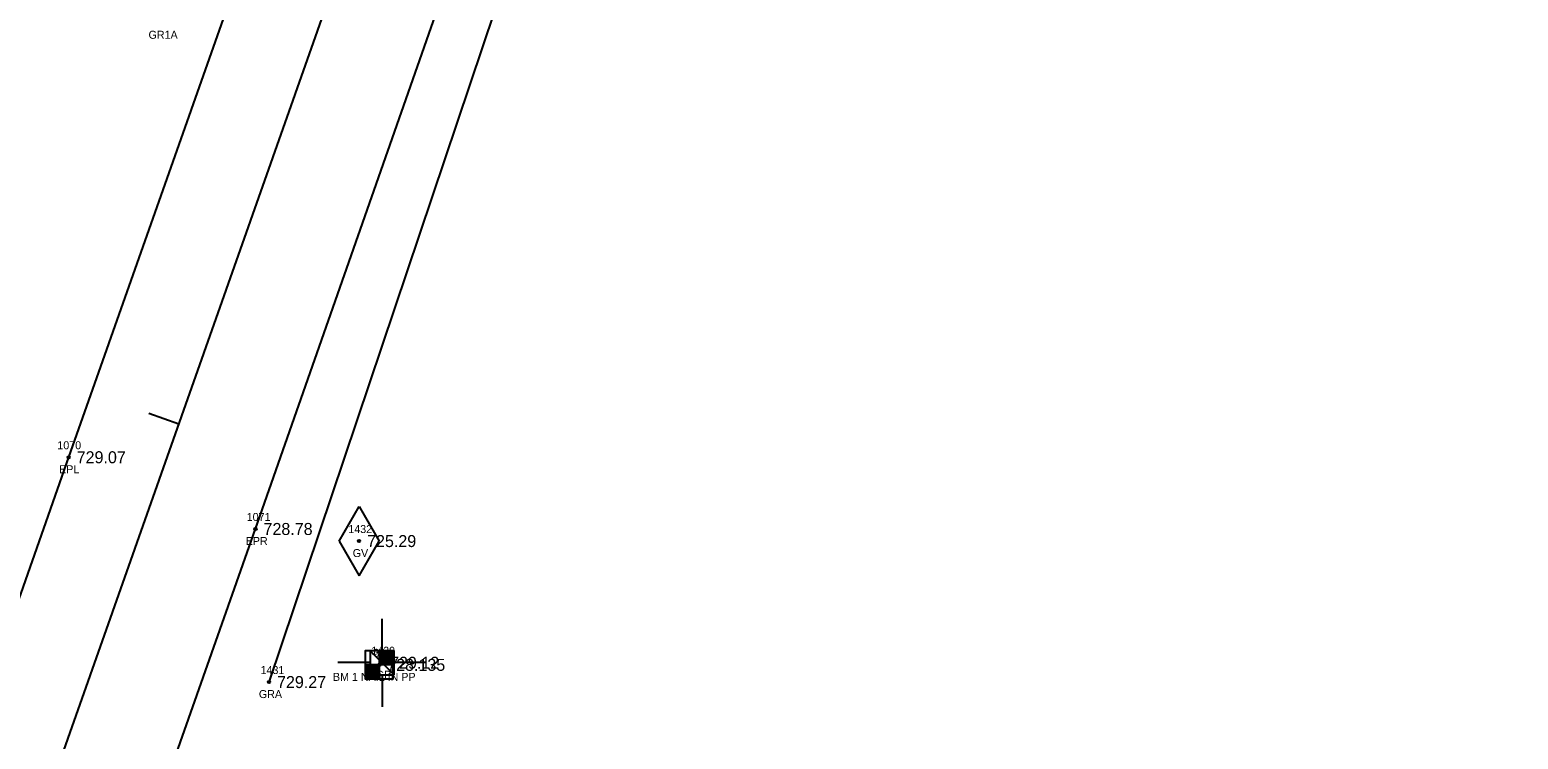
# Model space of a CAD drawing. Extents: x 1736563 to 1738032, y 1150548 to 1154248.
# Drawn here: x 1737322 to 1737508, y 1152422.1 to 1152510.8 of the extents above; entities that cross this region are included whole.
import ezdxf

# ---------------------------------------------------------------- set-up
doc = ezdxf.new("R2010")
doc.units = 0
for name, color, linetype in [('RD_EX_GuardRail', 7, 'Continuous'), ('RD_EX_GuardRail_txCode', 7, 'Continuous'), ('RD_EX_Road', 7, 'Continuous'), ('RD_EX_Road_txCode', 7, 'Continuous'), ('RD_EX_TX_GuardRail_ELEV', 7, 'Continuous'), ('RD_EX_TX_Road_ELEV', 7, 'Continuous'), ('RD_EX_TX_UT_ELEV', 7, 'Continuous'), ('RD_EX_UT', 7, 'Continuous'), ('RD_EX_UT_txCode', 7, 'Continuous'), ('RD_HC_Cl', 7, 'Continuous'), ('RD_HC_Data_Tic', 7, 'Continuous'), ('RD_HC_Survey', 7, 'Continuous'), ('RD_HC_Survey_ELEV', 7, 'Continuous'), ('RD_HC_Survey_txCode', 7, 'Continuous'), ('RD_SMD_Locator', 7, 'Continuous')]:
    doc.layers.add(name, color=color, linetype=linetype)

msp = doc.modelspace()

# ---------------------------------------------------------------- linework, layer by layer
at = {"layer": 'RD_EX_GuardRail'}
msp.add_lwpolyline([(1737351.87, 1152429.26), (1737391.13, 1152545.98), (1737408.34, 1152601.39), (1737428.16, 1152658.66), (1737456.13, 1152738.69), (1737462.06, 1152749.07), (1737464.76, 1152758.57), (1737497.67, 1152845.09)], dxfattribs=at)
at = {"layer": 'RD_EX_Road'}
for points in [[(1736868.01, 1151157.6), (1736882.54, 1151196.52), (1736892.4, 1151226.58), (1736911.77, 1151279.81), (1736926.32, 1151321.94), (1736959.92, 1151418.27), (1736977.6, 1151467.57), (1736993.86, 1151514.24), (1737026.63, 1151607.21), (1737059.17, 1151698.64), (1737091.53, 1151790.84), (1737119.9, 1151870.3), (1737125.51, 1151887.21), (1737129.74, 1151897.31), (1737157.61, 1151979.19), (1737191.07, 1152073.18), (1737224.57, 1152167.62), (1737258.08, 1152262.33), (1737292.51, 1152359.5), (1737326.83, 1152457.35), (1737361.84, 1152556.63), (1737380.81, 1152611.37), (1737392.07, 1152607.38)], [(1737114.69, 1151782.27), (1737149.29, 1151879.88), (1737171.36, 1151942.06), (1737180.55, 1151968.4), (1737214.61, 1152064.48), (1737248.04, 1152159.34), (1737281.83, 1152253.71), (1737315.68, 1152350.56), (1737350.18, 1152448.39), (1737384.95, 1152547.7), (1737404.17, 1152603.14), (1737392.07, 1152607.38)]]:
    msp.add_lwpolyline(points, dxfattribs=at)
at = {"layer": 'RD_EX_UT'}
for p, q in [((1737360.63, 1152446.88), (1737363.13, 1152451.21)), ((1737363.13, 1152451.21), (1737365.63, 1152446.88)), ((1737360.63, 1152446.88), (1737363.13, 1152442.55)), ((1737363.13, 1152442.55), (1737365.63, 1152446.88)), ((1737366, 1152433.17), (1737366, 1152437.17)), ((1737367.5, 1152433.17), (1737364.5, 1152430.17)), ((1737364.5, 1152433.17), (1737367.5, 1152430.17)), ((1737367.5, 1152433.17), (1737364.5, 1152433.17)), ((1737364.5, 1152433.17), (1737364.5, 1152430.17)), ((1737367.5, 1152430.17), (1737367.5, 1152433.17)), ((1737364.47, 1152431.71), (1737360.48, 1152431.71)), ((1737364.5, 1152430.17), (1737367.5, 1152430.17)), ((1737366, 1152430.17), (1737366, 1152426.17)), ((1737367.51, 1152431.73), (1737371.53, 1152431.73))]:
    msp.add_line(p, q, dxfattribs=at)
at = {"layer": 'RD_HC_Cl'}
msp.add_line((1736879.96, 1151154.46), (1737935.1, 1154148.31), dxfattribs=at)
at = {"layer": 'RD_HC_Data_Tic'}
msp.add_line((1737340.61, 1152461.5), (1737336.84, 1152462.83), dxfattribs=at)
at = {"layer": 'RD_HC_Survey'}
for p, q in [((1737365.64, 1152433.16), (1737365.64, 1152429.66)), ((1737365.66, 1152433.16), (1737365.66, 1152431.41)), ((1737365.69, 1152433.16), (1737365.69, 1152431.41)), ((1737365.71, 1152433.16), (1737365.71, 1152431.41)), ((1737365.74, 1152433.16), (1737365.74, 1152431.41)), ((1737365.76, 1152433.16), (1737365.76, 1152431.41)), ((1737365.79, 1152433.16), (1737365.79, 1152431.41)), ((1737365.81, 1152433.16), (1737365.81, 1152431.41)), ((1737365.84, 1152433.16), (1737365.84, 1152431.41)), ((1737365.86, 1152433.16), (1737365.86, 1152431.41)), ((1737365.89, 1152433.16), (1737365.89, 1152431.41)), ((1737365.91, 1152433.16), (1737365.91, 1152431.41)), ((1737365.93, 1152433.16), (1737365.93, 1152431.41)), ((1737365.96, 1152433.16), (1737365.96, 1152431.41)), ((1737365.98, 1152433.16), (1737365.98, 1152431.41)), ((1737366.01, 1152433.16), (1737366.01, 1152431.41)), ((1737366.03, 1152433.16), (1737366.03, 1152431.41)), ((1737366.06, 1152433.16), (1737366.06, 1152431.41)), ((1737366.08, 1152433.16), (1737366.08, 1152431.41)), ((1737366.11, 1152433.16), (1737366.11, 1152431.41)), ((1737366.13, 1152433.16), (1737366.13, 1152431.41)), ((1737366.16, 1152433.16), (1737366.16, 1152431.41)), ((1737366.18, 1152433.16), (1737366.18, 1152431.41)), ((1737366.21, 1152433.16), (1737366.21, 1152431.41)), ((1737366.23, 1152433.16), (1737366.23, 1152431.41)), ((1737366.26, 1152433.16), (1737366.26, 1152431.41)), ((1737366.28, 1152433.16), (1737366.28, 1152431.41)), ((1737366.31, 1152433.16), (1737366.31, 1152431.41)), ((1737366.33, 1152433.16), (1737366.33, 1152431.41)), ((1737366.36, 1152433.16), (1737366.36, 1152431.41)), ((1737366.38, 1152433.16), (1737366.38, 1152431.41)), ((1737366.4, 1152433.16), (1737366.4, 1152431.41)), ((1737366.43, 1152433.16), (1737366.43, 1152431.41)), ((1737366.45, 1152433.16), (1737366.45, 1152431.41)), ((1737366.48, 1152433.16), (1737366.48, 1152431.41)), ((1737366.5, 1152433.16), (1737366.5, 1152431.41)), ((1737366.53, 1152433.16), (1737366.53, 1152431.41)), ((1737366.55, 1152433.16), (1737366.55, 1152431.41)), ((1737366.58, 1152433.16), (1737366.58, 1152431.41)), ((1737366.6, 1152433.16), (1737366.6, 1152431.41)), ((1737366.63, 1152433.16), (1737366.63, 1152431.41)), ((1737366.65, 1152433.16), (1737366.65, 1152431.41)), ((1737366.68, 1152433.16), (1737366.68, 1152431.41)), ((1737366.7, 1152433.16), (1737366.7, 1152431.41)), ((1737366.73, 1152433.16), (1737366.73, 1152431.41)), ((1737366.75, 1152433.16), (1737366.75, 1152431.41)), ((1737366.78, 1152433.16), (1737366.78, 1152431.41)), ((1737366.8, 1152433.16), (1737366.8, 1152431.41)), ((1737366.83, 1152433.16), (1737366.83, 1152431.41)), ((1737366.85, 1152433.16), (1737366.85, 1152431.41)), ((1737366.87, 1152433.16), (1737366.87, 1152431.41)), ((1737366.9, 1152433.16), (1737366.9, 1152431.41)), ((1737366.92, 1152433.16), (1737366.92, 1152431.41)), ((1737366.95, 1152433.16), (1737366.95, 1152431.41)), ((1737366.97, 1152433.16), (1737366.97, 1152431.41)), ((1737367, 1152433.16), (1737367, 1152431.41)), ((1737367.02, 1152433.16), (1737367.02, 1152431.41)), ((1737367.05, 1152433.16), (1737367.05, 1152431.41)), ((1737367.07, 1152433.16), (1737367.07, 1152431.41)), ((1737367.1, 1152433.16), (1737367.1, 1152431.41)), ((1737367.12, 1152433.16), (1737367.12, 1152431.41)), ((1737367.15, 1152433.16), (1737367.15, 1152431.41)), ((1737367.17, 1152433.16), (1737367.17, 1152431.41)), ((1737367.2, 1152433.16), (1737367.2, 1152431.41)), ((1737367.22, 1152433.16), (1737367.22, 1152431.41)), ((1737367.25, 1152433.16), (1737367.25, 1152431.41)), ((1737367.27, 1152433.16), (1737367.27, 1152431.41)), ((1737367.3, 1152433.16), (1737367.3, 1152431.41)), ((1737367.32, 1152433.16), (1737367.32, 1152431.41)), ((1737367.35, 1152433.16), (1737367.35, 1152431.41)), ((1737367.37, 1152433.16), (1737367.37, 1152431.41)), ((1737367.39, 1152431.41), (1737363.89, 1152431.41)), ((1737363.89, 1152431.41), (1737363.89, 1152429.66)), ((1737363.92, 1152431.41), (1737363.92, 1152429.66)), ((1737363.94, 1152431.41), (1737363.94, 1152429.66)), ((1737363.97, 1152431.41), (1737363.97, 1152429.66)), ((1737363.99, 1152431.41), (1737363.99, 1152429.66)), ((1737364.02, 1152431.41), (1737364.02, 1152429.66)), ((1737364.04, 1152431.41), (1737364.04, 1152429.66)), ((1737364.07, 1152431.41), (1737364.07, 1152429.66)), ((1737364.09, 1152431.41), (1737364.09, 1152429.66)), ((1737364.12, 1152431.41), (1737364.12, 1152429.66)), ((1737364.14, 1152431.41), (1737364.14, 1152429.66)), ((1737364.17, 1152431.41), (1737364.17, 1152429.66)), ((1737364.19, 1152431.41), (1737364.19, 1152429.66)), ((1737364.22, 1152431.41), (1737364.22, 1152429.66)), ((1737364.24, 1152431.41), (1737364.24, 1152429.66)), ((1737364.27, 1152431.41), (1737364.27, 1152429.66)), ((1737364.29, 1152431.41), (1737364.29, 1152429.66)), ((1737364.32, 1152431.41), (1737364.32, 1152429.66)), ((1737364.34, 1152431.41), (1737364.34, 1152429.66)), ((1737364.36, 1152431.41), (1737364.36, 1152429.66)), ((1737364.39, 1152431.41), (1737364.39, 1152429.66)), ((1737364.41, 1152431.41), (1737364.41, 1152429.66)), ((1737364.44, 1152431.41), (1737364.44, 1152429.66)), ((1737364.46, 1152431.41), (1737364.46, 1152429.66)), ((1737364.49, 1152431.41), (1737364.49, 1152429.66)), ((1737364.51, 1152431.41), (1737364.51, 1152429.66)), ((1737364.54, 1152431.41), (1737364.54, 1152429.66)), ((1737364.56, 1152431.41), (1737364.56, 1152429.66)), ((1737364.59, 1152431.41), (1737364.59, 1152429.66)), ((1737364.61, 1152431.41), (1737364.61, 1152429.66)), ((1737364.64, 1152431.41), (1737364.64, 1152429.66)), ((1737364.66, 1152431.41), (1737364.66, 1152429.66)), ((1737364.69, 1152431.41), (1737364.69, 1152429.66)), ((1737364.71, 1152431.41), (1737364.71, 1152429.66)), ((1737364.74, 1152431.41), (1737364.74, 1152429.66)), ((1737364.76, 1152431.41), (1737364.76, 1152429.66)), ((1737364.79, 1152431.41), (1737364.79, 1152429.66)), ((1737364.81, 1152431.41), (1737364.81, 1152429.66)), ((1737364.84, 1152431.41), (1737364.84, 1152429.66)), ((1737364.86, 1152431.41), (1737364.86, 1152429.66)), ((1737364.88, 1152431.41), (1737364.88, 1152429.66)), ((1737364.91, 1152431.41), (1737364.91, 1152429.66)), ((1737364.93, 1152431.41), (1737364.93, 1152429.66)), ((1737364.96, 1152431.41), (1737364.96, 1152429.66)), ((1737364.98, 1152431.41), (1737364.98, 1152429.66)), ((1737365.01, 1152431.41), (1737365.01, 1152429.66)), ((1737365.03, 1152431.41), (1737365.03, 1152429.66)), ((1737365.06, 1152431.41), (1737365.06, 1152429.66)), ((1737365.08, 1152431.41), (1737365.08, 1152429.66)), ((1737365.11, 1152431.41), (1737365.11, 1152429.66)), ((1737365.13, 1152431.41), (1737365.13, 1152429.66)), ((1737365.16, 1152431.41), (1737365.16, 1152429.66)), ((1737365.18, 1152431.41), (1737365.18, 1152429.66)), ((1737365.21, 1152431.41), (1737365.21, 1152429.66)), ((1737365.23, 1152431.41), (1737365.23, 1152429.66)), ((1737365.26, 1152431.41), (1737365.26, 1152429.66)), ((1737365.28, 1152431.41), (1737365.28, 1152429.66)), ((1737365.31, 1152431.41), (1737365.31, 1152429.66)), ((1737365.33, 1152431.41), (1737365.33, 1152429.66)), ((1737365.35, 1152431.41), (1737365.35, 1152429.66)), ((1737365.38, 1152431.41), (1737365.38, 1152429.66)), ((1737365.4, 1152431.41), (1737365.4, 1152429.66)), ((1737365.43, 1152431.41), (1737365.43, 1152429.66)), ((1737365.45, 1152431.41), (1737365.45, 1152429.66)), ((1737365.48, 1152431.41), (1737365.48, 1152429.66)), ((1737365.5, 1152431.41), (1737365.5, 1152429.66)), ((1737365.53, 1152431.41), (1737365.53, 1152429.66)), ((1737365.55, 1152431.41), (1737365.55, 1152429.66)), ((1737365.58, 1152431.41), (1737365.58, 1152429.66)), ((1737365.6, 1152431.41), (1737365.6, 1152429.66)), ((1737365.63, 1152431.41), (1737365.63, 1152429.66))]:
    msp.add_line(p, q, dxfattribs=at)
msp.add_lwpolyline([(1737367.39, 1152433.16), (1737363.89, 1152433.16), (1737363.89, 1152429.66), (1737367.39, 1152429.66)], close=True, dxfattribs=at)
at = {"layer": 'RD_SMD_Locator'}
for centre in [(1737326.83, 1152457.35), (1737350.18, 1152448.39), (1737363.13, 1152446.88), (1737365.64, 1152431.41), (1737366, 1152431.67), (1737351.87, 1152429.26)]:
    msp.add_circle(centre, 0.15, dxfattribs=at)

# ---------------------------------------------------------------- texts
at = {"layer": 'RD_EX_GuardRail_txCode'}
for s, p in [('GR1A', (1737336.81, 1152509.65)), ('1431', (1737350.81, 1152430.26)), ('GRA', (1737350.6, 1152427.26))]:
    msp.add_text(s, height=1, dxfattribs=at).set_placement(p)
at = {"layer": 'RD_EX_Road_txCode'}
for s, p in [('1070', (1737325.41, 1152458.35)), ('EPL', (1737325.63, 1152455.35)), ('1071', (1737349.08, 1152449.39)), ('EPR', (1737348.95, 1152446.39))]:
    msp.add_text(s, height=1, dxfattribs=at).set_placement(p)
at = {"layer": 'RD_EX_TX_GuardRail_ELEV'}
msp.add_text('729.27', height=1.5, dxfattribs=at).set_placement((1737352.87, 1152428.51))
at = {"layer": 'RD_EX_TX_Road_ELEV'}
for s, p in [('729.07', (1737327.83, 1152456.6)), ('728.78', (1737351.18, 1152447.64))]:
    msp.add_text(s, height=1.5, dxfattribs=at).set_placement(p)
at = {"layer": 'RD_EX_TX_UT_ELEV'}
for s, p in [('725.29', (1737364.13, 1152446.13)), ('729.12', (1737367, 1152430.92))]:
    msp.add_text(s, height=1.5, dxfattribs=at).set_placement(p)
at = {"layer": 'RD_EX_UT_txCode'}
for s, p in [('1432', (1737361.78, 1152447.88)), ('GV', (1737362.33, 1152444.88)), ('1429', (1737364.65, 1152432.67)), ('GP', (1737365.22, 1152429.67))]:
    msp.add_text(s, height=1, dxfattribs=at).set_placement(p)
at = {"layer": 'RD_HC_Survey_ELEV'}
msp.add_text('728.135', height=1.5, dxfattribs=at).set_placement((1737366.64, 1152430.66))
at = {"layer": 'RD_HC_Survey_txCode'}
for s, p in [('33', (1737364.91, 1152432.41)), ('BM 1 NAIL IN PP', (1737359.86, 1152429.41))]:
    msp.add_text(s, height=1, dxfattribs=at).set_placement(p)

doc.saveas('drawing.dxf')
